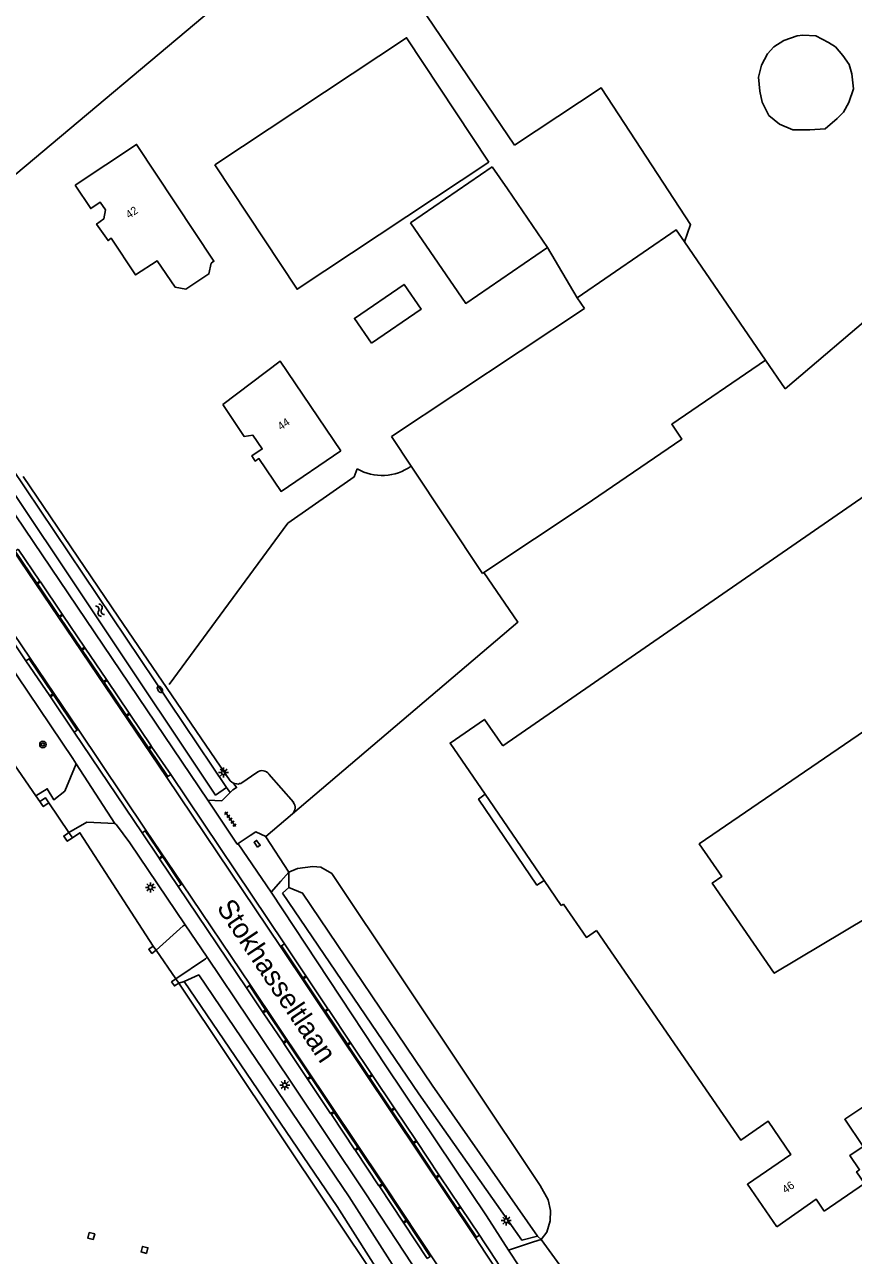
# Model space of a CAD drawing. Extents: x 133000 to 136000, y 400500 to 403500.
# Drawn here: x 133761.8 to 133865.4, y 400643 to 400796.8 of the extents above; entities that cross this region are included whole.
import ezdxf

# ---------------------------------------------------------------- set-up
doc = ezdxf.new("R2010")
doc.units = 0
for name, color, linetype in [('gg-afsc-draadraster', 7, 'Continuous'), ('gg-afsc-erfafscheiding', 7, 'Continuous'), ('gg-afsc-hekwerk', 7, 'Continuous'), ('gg-afsc-lijn draadraster', 7, 'Continuous'), ('gg-afsc-muur', 7, 'Continuous'), ('gg-anno-huisnummerreeks BGT', 7, 'Continuous'), ('gg-anno-openbare ruimte label', 7, 'Continuous'), ('gg-bbg-bijgebouw', 7, 'Continuous'), ('gg-bbg-gedigitaliseerde bebouwing', 7, 'Continuous'), ('gg-bbg-gedigitaliseerde bijgebouw', 7, 'Continuous'), ('gg-bbg-hoofdgebouw', 7, 'Continuous'), ('gg-bbg-hoogspanningsmast', 7, 'Continuous'), ('gg-bbg-onder overbouw', 7, 'Continuous'), ('gg-bbg-pand overbouw', 7, 'Continuous'), ('gg-knt-bronhoudergrens', 7, 'Continuous'), ('gg-knt-verharding', 7, 'Continuous'), ('gg-knt-verharding nz', 7, 'Continuous'), ('gg-kntw-bovenkant insteek waterloop', 7, 'Continuous'), ('gg-kntw-greppel-droge sloot', 7, 'Continuous'), ('gt-grn-groengrens', 7, 'Continuous'), ('gt-symb-boom', 7, 'Continuous'), ('gt-symb-brandkraan', 7, 'Continuous'), ('gt-symb-kolk center center', 7, 'Continuous'), ('gt-symb-lichtmast', 7, 'Continuous'), ('gt-symb-tegel verharding', 7, 'Continuous'), ('gt-symb-watersymbool', 7, 'Continuous')]:
    doc.layers.add(name, color=color, linetype=linetype)

# ---------------------------------------------------------------- blocks, each defined once
blk = doc.blocks.new('gt0-LMAST')
at = {"layer": 'gt-symb-lichtmast'}
for p, q in [((-0.18, 0.17), (-0.45, 0.44)), ((-0.01, 0.25), (-0.01, 0.62)), ((0.17, 0.17), (0.44, 0.44)), ((-0.26, 0), (-0.63, 0)), ((-0.18, -0.18), (-0.45, -0.45)), ((-0.01, -0.25), (-0.01, -0.63)), ((0.44, -0.45), (0.17, -0.18)), ((0.24, 0), (0.62, 0))]:
    blk.add_line(p, q, dxfattribs=at)
blk.add_circle((-0.01, 0), 0.25, dxfattribs=at)
blk = doc.blocks.new('gt0-BR')
at = {"layer": 'gt-symb-brandkraan'}
for centre, radius, start, end in [((-0.24, 0), 0.206, 107.5669, 252.4331), ((0.6, -2.66), 3, 106.892, 107.5669), ((0, -0.69), 0.938, 73.108, 106.892), ((-0.6, -2.66), 3, 72.4331, 73.108), ((0.24, 0), 0.206, 287.567, 72.4331), ((0.6, 2.66), 3, 252.4331, 253.108), ((0, 0.69), 0.938, 253.108, 286.8921), ((-0.6, 2.66), 3, 286.8921, 287.567)]:
    blk.add_arc(centre, radius, start, end, dxfattribs=at)
blk = doc.blocks.new('gt0-WA')
at = {"layer": 'gt-symb-watersymbool'}
for centre, start, end in [((-0.32, 0.02), 28.0725, 151.9275), ((0.43, 0.42), 208.0725, 331.9275), ((-0.32, -0.43), 28.0725, 151.9275), ((0.43, -0.03), 208.0725, 331.9275)]:
    blk.add_arc(centre, 0.425, start, end, dxfattribs=at)
blk = doc.blocks.new('gt0-BOOM')
at = {"layer": 'gt-symb-boom'}
for radius in [0.4, 0.2]:
    blk.add_circle((0, 0), radius, dxfattribs=at)
blk = doc.blocks.new('gt0-KOLKCC')
at = {"layer": 'gt-symb-kolk center center'}
blk.add_lwpolyline([(-0.38, 0.2), (0.38, 0.2), (0.38, -0.2), (-0.38, -0.2)], close=True, dxfattribs=at)
blk = doc.blocks.new('gt0-TEG1')
at = {"layer": 'gt-symb-tegel verharding'}
for p, q in [((-1.12, 0), (1.13, 0)), ((-0.9, -0.25), (-0.9, 0.25)), ((-0.45, -0.25), (-0.45, 0.25)), ((0, -0.25), (0, 0.25)), ((0.45, -0.25), (0.45, 0.25)), ((0.9, -0.25), (0.9, 0.25))]:
    blk.add_line(p, q, dxfattribs=at)

msp = doc.modelspace()

# ---------------------------------------------------------------- linework, layer by layer
at = {"layer": 'gg-afsc-draadraster'}
msp.add_line((133856.9, 400751.26), (133879.93, 400770.88), dxfattribs=at)
for points in [[(133745.11, 400764.98), (133802.03, 400812.78), (133823.07, 400781.7)], [(133836.14, 400785.49), (133845.1, 400771.77), (133844.32, 400769.62)]]:
    msp.add_lwpolyline(points, dxfattribs=at)
at = {"layer": 'gg-afsc-erfafscheiding'}
for p, q in [((133754.89, 400712.45), (133763.25, 400700.39)), ((133763.25, 400700.39), (133763.73, 400699.7)), ((133764.85, 400699.52), (133767.37, 400695.8)), ((133780.73, 400677.52), (133778.26, 400681.1)), ((133781.09, 400677.01), (133814.95, 400626.44))]:
    msp.add_line(p, q, dxfattribs=at)
msp.add_lwpolyline([(133767.81, 400695.16), (133768.74, 400695.78), (133777.88, 400681.62)], dxfattribs=at)
at = {"layer": 'gg-afsc-hekwerk'}
for p, q in [((133788.98, 400702.02), (133790.88, 400703.33)), ((133792.38, 400703.12), (133795.43, 400699.59))]:
    msp.add_line(p, q, dxfattribs=at)
for points in [[(133761.65, 400740.32), (133773.57, 400722.73), (133787.54, 400702.27)], [(133787.54, 400702.27), (133787.73, 400702.1), (133787.88, 400702.01), (133787.96, 400701.97)], [(133788.98, 400702.02), (133788.84, 400701.95), (133788.71, 400701.92), (133788.55, 400701.87), (133788.36, 400701.88), (133788.12, 400701.92), (133787.96, 400701.97)]]:
    msp.add_lwpolyline(points, dxfattribs=at)
for centre, radius, start, end in [((133791.53, 400702.48), 1.07, 36.9925, 127.2828), ((133794.6, 400698.94), 1.05, 311.3804, 38.3955)]:
    msp.add_arc(centre, radius, start, end, dxfattribs=at)
at = {"layer": 'gg-afsc-lijn draadraster'}
for p, q in [((133856.9, 400751.26), (133879.93, 400770.88)), ((133827.2, 400768.93), (133830.92, 400762.64))]:
    msp.add_line(p, q, dxfattribs=at)
for points in [[(133745.11, 400764.98), (133802.03, 400812.78), (133823.07, 400781.7)], [(133836.14, 400785.49), (133845.1, 400771.77), (133844.32, 400769.62)]]:
    msp.add_lwpolyline(points, dxfattribs=at)
at = {"layer": 'gg-afsc-muur'}
for p, q in [((133791.97, 400695.3), (133795.3, 400698.15)), ((133767.37, 400695.8), (133767.81, 400695.16)), ((133777.88, 400681.62), (133778.1, 400681.31)), ((133778.1, 400681.31), (133778.26, 400681.1)), ((133780.73, 400677.52), (133781.09, 400677.01))]:
    msp.add_line(p, q, dxfattribs=at)
for points in [[(133803.42, 400741.24), (133803.04, 400740.27), (133794.75, 400734.49), (133779.88, 400714.29)], [(133795.3, 400698.15), (133823.5, 400722.1), (133819.25, 400728.3)], [(133763.73, 400699.7), (133764.43, 400700.16), (133764.85, 400699.52)], [(133764.85, 400699.52), (133764.16, 400699.06), (133763.73, 400699.7)], [(133767.81, 400695.16), (133767.16, 400694.72), (133766.73, 400695.36), (133767.37, 400695.8)], [(133778.26, 400681.1), (133777.74, 400680.71), (133777.35, 400681.23), (133777.88, 400681.62)], [(133781.09, 400677.01), (133780.56, 400676.64), (133780.2, 400677.14), (133780.73, 400677.52)]]:
    msp.add_lwpolyline(points, dxfattribs=at)
msp.add_arc((133806.52, 400746.75), 6.32, 240.6229, 305.1358, dxfattribs=at)
at = {"layer": 'gg-bbg-bijgebouw'}
for p, q in [((133810.16, 400741.58), (133807.7, 400745.28)), ((133819.06, 400728.17), (133810.16, 400741.58))]:
    msp.add_line(p, q, dxfattribs=at)
at = {"layer": 'gg-bbg-gedigitaliseerde bebouwing'}
for points in [[(133781.99, 400763.7), (133784.87, 400765.61), (133785.14, 400766.95), (133785.5, 400767.19), (133775.83, 400781.79), (133768.15, 400776.7)], [(133801.37, 400743.49), (133793.77, 400754.73), (133786.6, 400749.31)]]:
    msp.add_lwpolyline(points, dxfattribs=at)
at = {"layer": 'gg-bbg-gedigitaliseerde bijgebouw'}
for p, q in [((133820.29, 400779.01), (133810.07, 400772.01)), ((133822.18, 400776.25), (133820.29, 400779.01)), ((133827.2, 400768.93), (133822.18, 400776.25)), ((133854.44, 400754.85), (133844.32, 400769.62)), ((133830.92, 400762.64), (133831.83, 400761.3)), ((133831.83, 400761.3), (133807.7, 400745.28)), ((133819.25, 400728.3), (133831.91, 400736.7)), ((133819.06, 400728.17), (133819.25, 400728.3))]:
    msp.add_line(p, q, dxfattribs=at)
for points in [[(133819.88, 400779.58), (133809.58, 400795.13), (133785.59, 400779.24)], [(133785.59, 400779.24), (133795.89, 400763.7), (133819.88, 400779.58)], [(133810.07, 400772.01), (133816.98, 400761.93), (133827.2, 400768.93)], [(133844.32, 400769.62), (133843.3, 400771.12), (133830.92, 400762.64)], [(133805.19, 400756.96), (133803.07, 400760.05), (133809.28, 400764.31), (133811.4, 400761.21), (133805.19, 400756.96)], [(133831.91, 400736.7), (133844, 400744.98), (133842.73, 400746.83), (133854.44, 400754.85)]]:
    msp.add_lwpolyline(points, dxfattribs=at)
at = {"layer": 'gg-bbg-hoofdgebouw'}
for q in [(133826.78, 400689.8), (133829.21, 400686.88)]:
    msp.add_line((133828.91, 400686.68), q, dxfattribs=at)
for points in [[(133768.15, 400776.7), (133770.1, 400773.77), (133771.29, 400774.56), (133771.93, 400773.61), (133771.72, 400772.48), (133770.82, 400771.85), (133772.27, 400769.79), (133772.67, 400770.07), (133775.71, 400765.48), (133778.39, 400767.26), (133780.64, 400763.97), (133781.99, 400763.7)], [(133786.6, 400749.31), (133789.27, 400745.3), (133790.37, 400745.45), (133791.53, 400743.74), (133790.23, 400742.88), (133790.66, 400742.23), (133791.12, 400742.53), (133793.9, 400738.44), (133801.37, 400743.49)], [(133821.6, 400706.66), (133873.81, 400742.68)], [(133873.4, 400713.03), (133846.17, 400694.39), (133848.98, 400690.31), (133847.79, 400689.49), (133855.56, 400678.22), (133876.14, 400690.52)], [(133819.4, 400700.59), (133815.03, 400706.98), (133819.31, 400709.94), (133821.6, 400706.66)], [(133829.21, 400686.88), (133832.06, 400682.7), (133833.31, 400683.57)], [(133833.31, 400683.57), (133851.36, 400657.38), (133854.8, 400659.73), (133857.63, 400655.59), (133852.19, 400651.87), (133855.89, 400646.56)], [(133861.81, 400648.5), (133866.84, 400651.94), (133865.84, 400653.43), (133866.21, 400653.67), (133865.01, 400655.46), (133866.67, 400656.59), (133864.37, 400659.98), (133867.14, 400661.82), (133866.95, 400662.1), (133886.26, 400673.77)], [(133855.89, 400646.56), (133860.8, 400649.98), (133861.81, 400648.5)]]:
    msp.add_lwpolyline(points, dxfattribs=at)
at = {"layer": 'gg-bbg-hoogspanningsmast'}
for points in [[(133770.4, 400644.95), (133770.59, 400645.65), (133769.91, 400645.83), (133769.72, 400645.13), (133770.4, 400644.95)], [(133777.06, 400643.22), (133777.25, 400643.92), (133776.57, 400644.1), (133776.39, 400643.4), (133777.06, 400643.22)]]:
    msp.add_lwpolyline(points, dxfattribs=at)
at = {"layer": 'gg-bbg-onder overbouw'}
msp.add_line((133826.78, 400689.8), (133819.4, 400700.59), dxfattribs=at)
at = {"layer": 'gg-bbg-pand overbouw'}
msp.add_lwpolyline([(133819.4, 400700.59), (133818.59, 400699.99), (133825.87, 400689.25), (133826.78, 400689.8)], dxfattribs=at)
at = {"layer": 'gg-knt-bronhoudergrens'}
msp.add_line((133854.44, 400754.85), (133856.9, 400751.26), dxfattribs=at)
for points in [[(133854.7, 400793.13), (133855.49, 400794), (133856.76, 400794.79), (133858.43, 400795.35), (133859.14, 400795.43), (133860.73, 400795.35), (133862.32, 400794.55), (133863.19, 400794), (133864.14, 400792.89), (133864.91, 400791.8), (133865.26, 400790.61), (133865.44, 400788.73), (133864.89, 400787.04), (133864.2, 400785.82), (133863.43, 400785.03), (133861.92, 400783.76), (133860.02, 400783.6), (133857.87, 400783.6), (133856.21, 400784.32), (133854.86, 400785.43), (133854.06, 400787.09), (133853.75, 400788.44), (133853.59, 400790.19), (133853.96, 400791.69), (133854.7, 400793.13)], [(133823.07, 400781.7), (133833.9, 400788.88), (133836.14, 400785.49)]]:
    msp.add_lwpolyline(points, dxfattribs=at)
at = {"layer": 'gg-knt-verharding'}
for p, q in [((133761.01, 400731.24), (133763.72, 400727.24)), ((133763.8, 400727.12), (133766.53, 400723.08)), ((133766.31, 400722.93), (133766.16, 400722.83)), ((133766.6, 400722.98), (133766.23, 400722.73)), ((133766.31, 400722.93), (133766.53, 400723.08)), ((133766.53, 400723.08), (133766.6, 400722.98)), ((133766.6, 400722.98), (133769.3, 400718.99)), ((133772.05, 400714.93), (133769.39, 400718.86)), ((133762.38, 400717.51), (133762, 400717.25)), ((133764.97, 400712.88), (133762, 400717.25)), ((133774.9, 400710.72), (133772.13, 400714.81)), ((133765.05, 400712.76), (133768.04, 400708.37)), ((133777.67, 400706.63), (133774.98, 400710.6)), ((133768.04, 400708.37), (133768.4, 400708.62)), ((133777.75, 400706.5), (133780.09, 400703.06)), ((133768.26, 400704.38), (133766.87, 400700.97)), ((133773.09, 400696.96), (133768.26, 400704.38)), ((133780.09, 400703.06), (133779.72, 400702.8)), ((133784.73, 400699.87), (133788.42, 400694.38)), ((133786.87, 400700.16), (133787.51, 400700.81)), ((133769.59, 400697.12), (133767.37, 400695.8)), ((133773.09, 400696.96), (133769.59, 400697.12)), ((133776.52, 400695.78), (133776.9, 400696.03)), ((133778.64, 400692.63), (133776.52, 400695.78)), ((133790.03, 400695.45), (133788.42, 400694.38)), ((133781.04, 400689.08), (133778.7, 400692.51)), ((133793.86, 400689.73), (133794.88, 400690.87)), ((133781.42, 400689.34), (133781.04, 400689.08)), ((133792.64, 400688.36), (133793.86, 400689.73)), ((133784.67, 400680.24), (133781.9, 400684.3)), ((133794.31, 400681.89), (133793.95, 400681.64)), ((133794.31, 400681.89), (133797, 400677.89)), ((133797.07, 400677.77), (133799.75, 400673.78)), ((133789.57, 400676.42), (133789.95, 400676.69)), ((133791.58, 400673.42), (133789.57, 400676.42)), ((133794.14, 400669.6), (133791.67, 400673.29)), ((133799.82, 400673.68), (133802.55, 400669.6)), ((133797.16, 400665.09), (133794.22, 400669.47)), ((133802.62, 400669.49), (133805.25, 400665.56)), ((133800.09, 400660.71), (133797.25, 400664.96)), ((133805.33, 400665.45), (133808.03, 400661.41)), ((133803.11, 400656.18), (133800.18, 400660.58)), ((133808.11, 400661.29), (133810.77, 400657.32)), ((133813.63, 400653.05), (133810.85, 400657.2)), ((133806.13, 400651.68), (133803.19, 400656.07)), ((133813.71, 400652.93), (133816.28, 400649.1)), ((133809.15, 400647.12), (133806.22, 400651.53)), ((133816.36, 400648.97), (133818.68, 400645.5)), ((133812.14, 400642.6), (133809.23, 400647)), ((133818.68, 400645.5), (133818.31, 400645.25)), ((133825.47, 400644.66), (133822.34, 400643.63)), ((133826.41, 400644.97), (133825.47, 400644.66)), ((133831.29, 400638.28), (133826.41, 400644.97)), ((133822.34, 400643.63), (133827.62, 400635.58))]:
    msp.add_line(p, q, dxfattribs=at)
for points in [[(133746.7, 400756.13), (133758.51, 400738.61), (133784.73, 400699.87)], [(133763.72, 400727.24), (133763.35, 400726.99), (133760.64, 400730.98), (133761.01, 400731.24)], [(133766.16, 400722.83), (133763.42, 400726.87), (133763.8, 400727.12)], [(133769.3, 400718.99), (133768.93, 400718.74), (133766.23, 400722.73)], [(133768.26, 400704.38), (133767.85, 400705.08), (133758.04, 400719.6)], [(133769.39, 400718.86), (133769.02, 400718.61), (133771.69, 400714.69), (133772.05, 400714.93)], [(133762.38, 400717.51), (133765.34, 400713.13), (133764.97, 400712.88)], [(133772.13, 400714.81), (133771.78, 400714.57), (133774.53, 400710.47), (133774.9, 400710.72)], [(133768.4, 400708.62), (133765.43, 400713.01), (133765.05, 400712.76)], [(133774.98, 400710.6), (133774.61, 400710.36), (133777.3, 400706.39), (133777.67, 400706.63)], [(133779.72, 400702.8), (133777.4, 400706.26), (133777.75, 400706.5)], [(133787.51, 400700.81), (133787.85, 400701.14), (133788.33, 400701.42), (133787.96, 400701.97)], [(133763.25, 400700.39), (133764.66, 400701.28), (133765.48, 400699.9), (133766.87, 400700.97)], [(133784.73, 400699.87), (133786.48, 400699.78), (133786.87, 400700.16)], [(133781.9, 400684.3), (133774.97, 400694.51), (133773.3, 400696.77), (133773.09, 400696.96)], [(133776.9, 400696.03), (133779.01, 400692.9), (133778.64, 400692.63)], [(133791.97, 400695.3), (133790.73, 400695.91), (133790.03, 400695.45)], [(133794.88, 400690.87), (133791.98, 400695.29), (133791.97, 400695.3)], [(133788.42, 400694.38), (133788.43, 400694.36), (133788.51, 400694.4), (133792.64, 400688.36)], [(133778.7, 400692.51), (133779.1, 400692.77), (133781.42, 400689.34)], [(133792.64, 400688.36), (133807.07, 400666.55), (133819.58, 400647.91), (133822.34, 400643.63)], [(133781.9, 400684.3), (133781.65, 400684.15), (133778.26, 400681.1)], [(133793.95, 400681.64), (133796.63, 400677.64), (133797, 400677.89)], [(133784.67, 400680.24), (133784.43, 400680.05), (133780.73, 400677.52)], [(133784.67, 400680.24), (133795.08, 400664.75), (133804.39, 400650.78), (133810.24, 400641.92), (133815.76, 400633.4), (133821.15, 400624.47), (133826.13, 400615.39), (133830.54, 400606.11), (133834.65, 400596.48), (133838.28, 400586.89), (133841.19, 400577.86), (133843.46, 400569.09), (133843.6, 400568.27)], [(133799.75, 400673.78), (133799.38, 400673.53), (133796.7, 400677.53), (133797.07, 400677.77)], [(133789.95, 400676.69), (133791.95, 400673.67), (133791.58, 400673.42)], [(133791.67, 400673.29), (133792.05, 400673.52), (133794.53, 400669.86), (133794.14, 400669.6)], [(133802.55, 400669.6), (133802.18, 400669.35), (133799.45, 400673.43), (133799.82, 400673.68)], [(133794.22, 400669.47), (133794.6, 400669.73), (133797.55, 400665.34), (133797.16, 400665.09)], [(133805.25, 400665.56), (133804.88, 400665.32), (133802.25, 400669.25), (133802.62, 400669.49)], [(133797.25, 400664.96), (133797.64, 400665.2), (133800.47, 400660.97), (133800.09, 400660.71)], [(133808.03, 400661.41), (133807.66, 400661.16), (133804.96, 400665.2), (133805.33, 400665.45)], [(133800.18, 400660.58), (133800.55, 400660.84), (133803.5, 400656.45), (133803.11, 400656.18)], [(133810.77, 400657.32), (133810.4, 400657.07), (133807.74, 400661.04), (133808.11, 400661.29)], [(133810.85, 400657.2), (133810.48, 400656.95), (133813.26, 400652.81), (133813.63, 400653.05)], [(133803.19, 400656.07), (133803.56, 400656.32), (133806.51, 400651.91), (133806.13, 400651.68)], [(133816.28, 400649.1), (133815.91, 400648.85), (133813.34, 400652.68), (133813.71, 400652.93)], [(133806.22, 400651.53), (133806.6, 400651.79), (133809.52, 400647.36), (133809.15, 400647.12)], [(133818.31, 400645.25), (133815.99, 400648.72), (133816.36, 400648.97)], [(133809.23, 400647), (133809.62, 400647.25), (133812.54, 400642.85), (133812.14, 400642.6)]]:
    msp.add_lwpolyline(points, dxfattribs=at)
at = {"layer": 'gg-knt-verharding nz'}
for p, q in [((133746.61, 400751.42), (133779.59, 400702.71)), ((133762, 400717.25), (133753.72, 400729.55)), ((133762.52, 400717.6), (133754.2, 400729.88)), ((133763.8, 400727.12), (133763.72, 400727.24)), ((133769.39, 400718.86), (133769.3, 400718.99)), ((133762.38, 400717.51), (133762.52, 400717.6)), ((133768.54, 400708.71), (133762.52, 400717.6)), ((133772.13, 400714.81), (133772.05, 400714.93)), ((133765.05, 400712.76), (133764.97, 400712.88)), ((133774.98, 400710.6), (133774.9, 400710.72)), ((133768.04, 400708.37), (133776.52, 400695.78)), ((133768.4, 400708.62), (133768.54, 400708.71)), ((133768.54, 400708.71), (133777, 400696.1)), ((133777.75, 400706.5), (133777.67, 400706.63)), ((133780.09, 400703.06), (133794.31, 400681.89)), ((133779.59, 400702.71), (133779.72, 400702.8)), ((133779.59, 400702.71), (133793.83, 400681.56)), ((133777, 400696.1), (133776.9, 400696.03)), ((133777, 400696.1), (133781.54, 400689.41)), ((133778.64, 400692.63), (133778.7, 400692.51)), ((133781.54, 400689.41), (133781.42, 400689.34)), ((133781.54, 400689.41), (133790.05, 400676.76)), ((133781.04, 400689.08), (133789.57, 400676.42)), ((133793.83, 400681.56), (133793.95, 400681.64)), ((133793.83, 400681.56), (133818.18, 400645.16)), ((133797.07, 400677.77), (133797, 400677.89)), ((133789.95, 400676.69), (133790.05, 400676.76)), ((133799.82, 400673.68), (133799.75, 400673.78)), ((133791.58, 400673.42), (133791.67, 400673.29)), ((133794.14, 400669.6), (133794.22, 400669.47)), ((133802.62, 400669.49), (133802.55, 400669.6)), ((133797.16, 400665.09), (133797.25, 400664.96)), ((133805.33, 400665.45), (133805.25, 400665.56)), ((133808.11, 400661.29), (133808.03, 400661.41)), ((133800.09, 400660.71), (133800.18, 400660.58)), ((133810.85, 400657.2), (133810.77, 400657.32)), ((133803.11, 400656.18), (133803.19, 400656.07)), ((133813.71, 400652.93), (133813.63, 400653.05)), ((133806.13, 400651.68), (133806.22, 400651.53)), ((133816.36, 400648.97), (133816.28, 400649.1)), ((133809.15, 400647.12), (133809.23, 400647)), ((133818.18, 400645.16), (133818.31, 400645.25))]:
    msp.add_line(p, q, dxfattribs=at)
msp.add_lwpolyline([(133790.05, 400676.76), (133806.68, 400651.92), (133815.7, 400638.33), (133818.58, 400633.77), (133821.4, 400629.18), (133824.17, 400624.45), (133826.81, 400619.68), (133829.32, 400614.84), (133831.71, 400609.99), (133834.03, 400605.03), (133836.32, 400599.7), (133838.35, 400594.59), (133840.17, 400589.68), (133841.94, 400584.48), (133843.59, 400579.25), (133844.98, 400574.51), (133846.3, 400569.63)], dxfattribs=at)
for centre, radius, start, end in [((133552.17, 400467.43), 319.93, 30.4284, 33.7488), ((133568.57, 400477.88), 301.09, 30.2924, 33.8282)]:
    msp.add_arc(centre, radius, start, end, dxfattribs=at)
at = {"layer": 'gg-kntw-bovenkant insteek waterloop'}
msp.add_line((133758.36, 400744.08), (133787.07, 400701.46), dxfattribs=at)
for points in [[(133787.07, 400701.46), (133785.71, 400700.49), (133757.24, 400743.06), (133757.86, 400743.62)], [(133781.79, 400677.21), (133783.6, 400678.02), (133802.4, 400650.3), (133818.31, 400625.4)], [(133815.2, 400626.6), (133800.89, 400649.09), (133781.79, 400677.21)]]:
    msp.add_lwpolyline(points, dxfattribs=at)
at = {"layer": 'gg-kntw-greppel-droge sloot'}
msp.add_line((133794.05, 400688.24), (133794.87, 400688.93), dxfattribs=at)
for points in [[(133825.94, 400645.36), (133824.01, 400644.86), (133811.11, 400663.17), (133794.05, 400688.24)], [(133794.87, 400688.93), (133796.59, 400688.25), (133812.8, 400664.26), (133825.94, 400645.36)]]:
    msp.add_lwpolyline(points, dxfattribs=at)
at = {"layer": 'gt-grn-groengrens'}
for p, q in [((133787.51, 400700.81), (133787.07, 400701.46)), ((133794.87, 400688.93), (133794.88, 400690.87)), ((133781.79, 400677.21), (133781.09, 400677.01)), ((133825.94, 400645.36), (133826.41, 400644.97)), ((133827.12, 400645.86), (133826.41, 400644.97))]:
    msp.add_line(p, q, dxfattribs=at)
msp.add_lwpolyline([(133794.88, 400690.87), (133795.96, 400691.3), (133797.87, 400691.58), (133798.86, 400691.49), (133800.22, 400690.69), (133826.27, 400651.72), (133827.29, 400649.93), (133827.58, 400648.58), (133827.53, 400647.29), (133827.12, 400645.86)], dxfattribs=at)

# ---------------------------------------------------------------- block references
at = {"layer": 'gt-symb-boom'}
msp.add_blockref('gt0-BOOM', (133764.11, 400706.81), dxfattribs=at)
at = {"layer": 'gt-symb-brandkraan', "rotation": -56.3734708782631}
msp.add_blockref('gt0-BR', (133778.75, 400713.7), dxfattribs=at)
at = {"layer": 'gt-symb-kolk center center', "rotation": 126.4486364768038}
msp.add_blockref('gt0-KOLKCC', (133790.9, 400694.41), dxfattribs=at)
at = {"layer": 'gt-symb-lichtmast'}
for p in [(133786.71, 400703.3), (133777.56, 400688.96), (133794.36, 400664.26), (133822.05, 400647.32)]:
    msp.add_blockref('gt0-LMAST', p, dxfattribs=at)
at = {"layer": 'gt-symb-tegel verharding', "rotation": -55.721733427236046}
msp.add_blockref('gt0-TEG1', (133787.55, 400697.48), dxfattribs=at)
at = {"layer": 'gt-symb-watersymbool', "rotation": -60.511092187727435}
msp.add_blockref('gt0-WA', (133771.24, 400723.63), dxfattribs=at)

# ---------------------------------------------------------------- texts
at = {"layer": 'gg-anno-huisnummerreeks BGT'}
for s, rotation, p in [('42', 34, (133774.88, 400772.48)), ('44', 34.1, (133793.87, 400746.03)), ('46', 34.9, (133856.96, 400650.66))]:
    msp.add_text(s, height=1, rotation=rotation, dxfattribs=at).set_placement(p)
at = {"layer": 'gg-anno-openbare ruimte label'}
msp.add_text('Stokhasseltlaan', height=2.5, rotation=303.8, dxfattribs=at).set_placement((133785.76, 400686.43))

doc.saveas('drawing.dxf')
